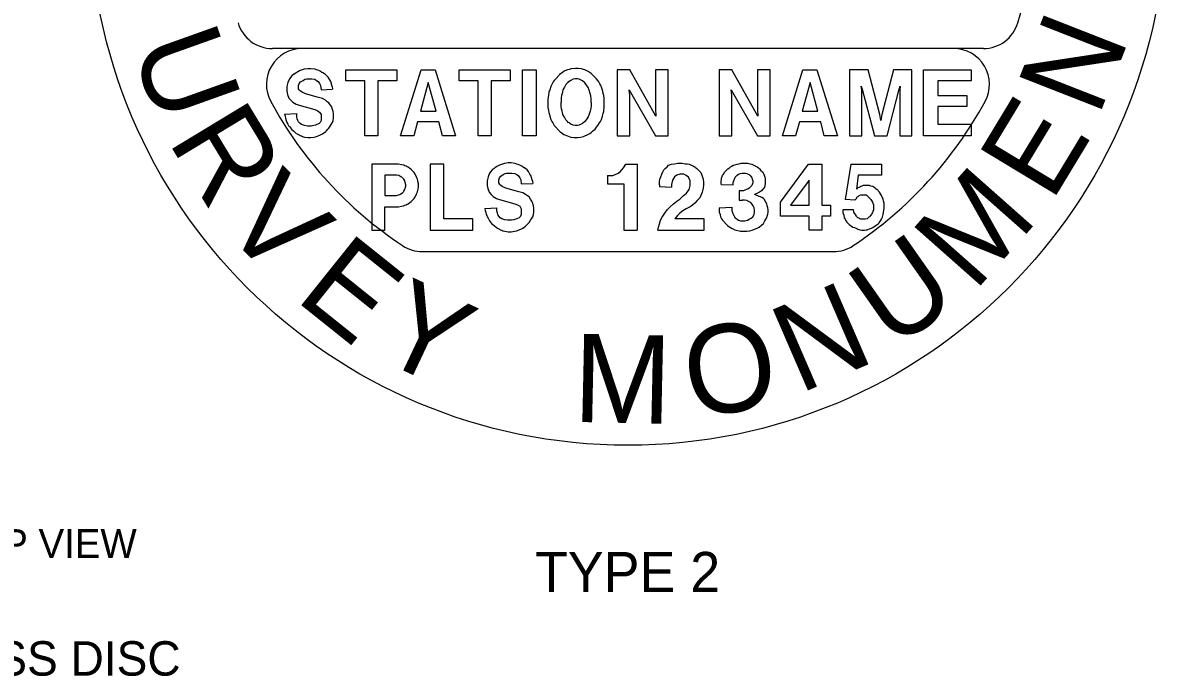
# Model space of a CAD drawing. Extents: x 99862 to 103151, y 100000 to 102076.
# Drawn here: x 100680 to 101477, y 101164 to 101619 of the extents above; entities that cross this region are included whole.
import ezdxf

# ---------------------------------------------------------------- set-up
doc = ezdxf.new("R2010")
doc.units = 0
for name, color, linetype in [('Level 10', 7, 'Continuous'), ('Level 13', 7, 'Continuous'), ('Level 18', 7, 'Continuous'), ('Level 20', 7, 'Continuous'), ('Level 6', 7, 'Continuous')]:
    doc.layers.add(name, color=color, linetype=linetype)

msp = doc.modelspace()

# ---------------------------------------------------------------- linework, layer by layer
at = {"layer": 'Level 13'}
msp.add_line((100958.36, 101459.97), (101244.7, 101459.97), dxfattribs=at)
msp.add_lwpolyline([(101328.45, 101601.53), (100874.62, 101601.53)], dxfattribs=at)
for centre, radius, start, end in [((100874.62, 101576.53), 25, 90, 208.55165), ((101328.45, 101576.53), 25, 331.44835, 90), ((101101.53, 101700), 283.33, 208.55165, 236.34284), ((101101.53, 101700), 283.33, 303.65716, 331.44835), ((100958.36, 101484.97), 25, 236.34284, 270), ((101244.7, 101484.97), 25, 270.00017, 303.65716)]:
    msp.add_arc(centre, radius, start, end, dxfattribs=at)
at = {"layer": 'Level 18'}
msp.add_lwpolyline([(101349.19, 101601.53), (101101.53, 101601.53), (100853.87, 101601.53)], dxfattribs=at)
for centre, radius, start, end in [((101101.53, 101700), 283.33, 343.47705, 20.06426), ((100853.87, 101626.53), 25, 196.52295, 270), ((101349.19, 101626.53), 25, 270, 343.47705)]:
    msp.add_arc(centre, radius, start, end, dxfattribs=at)
at = {"layer": 'Level 20'}
for points in [[(100868.75, 101583.69), (100867.39, 101582.61), (100865.7, 101580.43), (100864.68, 101577.9), (100864.01, 101575), (100864.01, 101571.74), (100864.35, 101569.57), (100865.36, 101567.03), (100866.72, 101565.58), (100868.07, 101564.14), (100870.44, 101562.69), (100872.47, 101561.96), (100883.31, 101559.06), (100885, 101558.33), (100886.69, 101557.25)], [(100868.75, 101583.69), (100869.76, 101584.42), (100870.78, 101585.14), (100871.46, 101585.51), (100872.81, 101586.23), (100874.84, 101586.96), (100876.19, 101587.31), (100878.57, 101587.67), (100879.24, 101587.67), (100880.6, 101587.67), (100883.31, 101587.31), (100884.32, 101586.96), (100885.34, 101586.59), (100887.03, 101585.87), (100888.39, 101585.14), (100889.06, 101584.78), (100890.08, 101584.06)], [(100895.5, 101575), (100894.48, 101578.62), (100893.8, 101579.71), (100892.79, 101581.52), (100891.77, 101582.61), (100890.08, 101584.06)], [(100905.07, 101586.59), (100940.62, 101586.59), (100940.62, 101578.98), (100927.41, 101578.98), (100927.41, 101540.59), (100918.27, 101540.59), (100918.27, 101578.98), (100905.07, 101578.98), (100905.07, 101586.59)], [(100943.17, 101540.59), (100957.39, 101586.59), (100967.21, 101586.59), (100981.43, 101540.59), (100972.29, 101540.59), (100969.91, 101550.37), (100955.02, 101550.37), (100952.31, 101540.59), (100943.17, 101540.59)], [(100983.99, 101586.59), (101019.54, 101586.59), (101019.54, 101578.98), (101006.34, 101578.98), (101006.34, 101540.59), (100997.2, 101540.59), (100997.2, 101578.98), (100983.99, 101578.98), (100983.99, 101586.59)], [(101028.1, 101540.59), (101028.1, 101586.59), (101037.58, 101586.59), (101037.58, 101540.59), (101028.1, 101540.59)], [(101065.44, 101587.67), (101062.06, 101587.31), (101060.7, 101586.96), (101059.34, 101586.59), (101057.65, 101585.87), (101056.97, 101585.51), (101055.96, 101584.78), (101054.95, 101584.06), (101053.93, 101583.33), (101053.59, 101582.97), (101051.22, 101580.43), (101050.21, 101579.35), (101049.52, 101578.26), (101048.85, 101576.81), (101047.83, 101575), (101047.16, 101572.83), (101046.48, 101571.01), (101046.14, 101568.85), (101045.8, 101566.31), (101045.8, 101564.49), (101045.8, 101563.41)], [(101085.08, 101563.41), (101085.08, 101565.58), (101085.08, 101566.67), (101084.74, 101568.85), (101084.4, 101570.29), (101084.06, 101571.74), (101083.39, 101573.91), (101082.71, 101575.73), (101082.03, 101576.81), (101081.35, 101578.26), (101080.68, 101579.35), (101079.66, 101580.43), (101077.63, 101582.61), (101075.94, 101584.06), (101073.9, 101585.51), (101071.53, 101586.59), (101070.52, 101586.96), (101069.17, 101587.31), (101066.79, 101587.67), (101065.1, 101587.67)], [(101093.98, 101586.59), (101093.98, 101540.59), (101102.78, 101540.59), (101102.78, 101569.2), (101102.44, 101572.83), (101120.72, 101540.59), (101129.53, 101540.59), (101129.53, 101586.59), (101120.72, 101586.59), (101120.72, 101559.42), (101121.06, 101554.35), (101102.78, 101586.59), (101093.98, 101586.59)], [(101165.08, 101586.59), (101165.08, 101540.59), (101173.88, 101540.59), (101173.88, 101569.2), (101173.55, 101572.83), (101191.82, 101540.59), (101200.63, 101540.59), (101200.63, 101586.59), (101191.82, 101586.59), (101191.82, 101559.42), (101192.16, 101554.35), (101173.88, 101586.59), (101165.08, 101586.59)], [(101209.19, 101540.59), (101223.41, 101586.59), (101233.23, 101586.59), (101247.45, 101540.59), (101238.31, 101540.59), (101235.93, 101550.37), (101221.04, 101550.37), (101218.33, 101540.59), (101209.19, 101540.59)], [(101256.01, 101586.59), (101256.01, 101540.59), (101264.47, 101540.59), (101264.47, 101572.46), (101264.13, 101575.36), (101264.81, 101573.19), (101273.28, 101540.59), (101282.08, 101540.59), (101290.54, 101573.19), (101291.22, 101575.36), (101290.88, 101572.46), (101290.88, 101540.59), (101299.35, 101540.59), (101299.35, 101586.59), (101286.48, 101586.59), (101278.35, 101555.44), (101277.68, 101551.46), (101277, 101555.44), (101268.87, 101586.59), (101256.01, 101586.59)], [(101307.57, 101540.59), (101307.57, 101586.59), (101340.75, 101586.59), (101340.75, 101578.98), (101317.38, 101578.98), (101317.38, 101568.85), (101337.7, 101568.85), (101337.7, 101561.24), (101317.38, 101561.24), (101317.38, 101548.92), (101340.75, 101548.92), (101340.75, 101540.59), (101307.57, 101540.59)], [(100872.13, 101573.55), (100872.13, 101575.73), (100872.47, 101577.17), (100873.48, 101578.26), (100875.18, 101579.35), (100876.53, 101580.07), (100877.55, 101580.43), (100879.24, 101580.43), (100881.27, 101580.43), (100883.31, 101580.07), (100884.66, 101579.35), (100885.68, 101578.62), (100886.69, 101577.17), (100887.37, 101575.73), (100887.71, 101572.83)], [(100962.47, 101577.9), (100957.05, 101557.98), (100967.89, 101557.98), (100962.47, 101577.9)], [(101075.94, 101564.14), (101075.94, 101564.86), (101075.94, 101566.67), (101075.6, 101568.48), (101075.26, 101570.29), (101074.58, 101572.46), (101073.9, 101574.28), (101072.55, 101576.45), (101071.53, 101577.53), (101069.84, 101578.98), (101068.49, 101579.71), (101067.47, 101580.07), (101066.46, 101580.43), (101065.78, 101580.43), (101064.76, 101580.43), (101063.41, 101580.07), (101061.72, 101579.35), (101060.7, 101578.62), (101060.02, 101578.26), (101059.34, 101577.53), (101058.67, 101576.81), (101058.33, 101576.45), (101057.31, 101574.64), (101056.3, 101572.83), (101055.96, 101571.38), (101055.62, 101570.29), (101055.28, 101568.85), (101054.95, 101567.39), (101054.95, 101566.31), (101054.95, 101564.86), (101054.95, 101564.14)], [(101228.49, 101577.9), (101223.06, 101557.98), (101233.9, 101557.98), (101228.49, 101577.9)], [(100895.5, 101549.65), (100895.83, 101550.01), (100896.17, 101551.46), (100896.51, 101553.27), (100896.51, 101555.08), (100896.51, 101556.17), (100896.17, 101557.62), (100895.5, 101559.79), (100895.16, 101560.87), (100894.14, 101562.32), (100893.13, 101563.77), (100892.11, 101564.49), (100890.75, 101565.58), (100888.73, 101566.67), (100886.01, 101567.39), (100884.32, 101567.76), (100876.88, 101569.93), (100874.5, 101571.01), (100873.48, 101571.74), (100872.81, 101572.46), (100872.13, 101573.55)], [(100887.71, 101572.83), (100895.83, 101573.19)], [(100895.5, 101575), (100895.83, 101573.19)], [(101045.8, 101563.41), (101045.8, 101562.32), (101045.8, 101560.51), (101046.14, 101558.33), (101046.48, 101556.89), (101046.82, 101555.44), (101047.16, 101554.35), (101047.83, 101552.18), (101048.51, 101550.73), (101049.19, 101549.65), (101050.21, 101547.83), (101050.88, 101547.11), (101053.59, 101544.21), (101054.27, 101543.49), (101055.96, 101542.4), (101056.97, 101541.67), (101057.65, 101541.31), (101058.67, 101540.96), (101059.34, 101540.59), (101060.7, 101540.23), (101061.72, 101539.87), (101064.08, 101539.51), (101065.78, 101539.51), (101066.46, 101539.51), (101068.49, 101539.87), (101070.52, 101540.23), (101071.53, 101540.59), (101073.23, 101541.31), (101074.92, 101542.4), (101075.94, 101543.12), (101076.95, 101543.85), (101078.65, 101545.3), (101079.66, 101546.75), (101080.68, 101547.83), (101081.69, 101549.65), (101082.37, 101550.73), (101083.04, 101552.18), (101083.73, 101554.35), (101084.4, 101556.17), (101084.74, 101557.62), (101085.08, 101560.87), (101085.08, 101563.41)], [(101065.78, 101547.83), (101064.76, 101547.83), (101063.41, 101548.2), (101061.72, 101548.92), (101060.7, 101549.65), (101060.02, 101550.01), (101059.34, 101550.73), (101058.67, 101551.46), (101058.33, 101551.82), (101057.31, 101553.63), (101056.3, 101555.44), (101055.96, 101556.89), (101055.62, 101557.98), (101055.28, 101559.42), (101054.95, 101560.87), (101054.95, 101561.96), (101054.95, 101563.41), (101054.95, 101564.14)], [(101075.94, 101564.14), (101075.94, 101563.41), (101075.94, 101561.6), (101075.6, 101559.79), (101075.26, 101557.98), (101074.58, 101555.8), (101073.9, 101553.99), (101072.55, 101551.82), (101071.53, 101550.73), (101069.84, 101549.28), (101068.49, 101548.56), (101067.47, 101548.2), (101066.46, 101547.83), (101065.78, 101547.83)], [(100862.31, 101555.8), (100870.78, 101556.17)], [(100862.31, 101555.8), (100862.66, 101554.35), (100862.99, 101552.9), (100863.33, 101551.46), (100863.67, 101550.73), (100864.01, 101550.01), (100864.68, 101548.92), (100865.36, 101547.47), (100865.7, 101547.11), (100867.05, 101545.3), (100868.75, 101543.85), (100870.44, 101542.4), (100871.12, 101542.04), (100872.47, 101541.31), (100873.15, 101540.96), (100874.17, 101540.59), (100874.84, 101540.23), (100876.19, 101539.87), (100878.57, 101539.51), (100879.58, 101539.51), (100880.6, 101539.51), (100882.97, 101539.87), (100884.66, 101540.23), (100885.68, 101540.59), (100887.37, 101541.31), (100888.73, 101542.04), (100889.74, 101542.76), (100890.75, 101543.49), (100891.44, 101544.21), (100892.45, 101545.3), (100893.13, 101546.02), (100894.14, 101547.47), (100894.82, 101548.56), (100895.5, 101549.65)], [(100883.98, 101548.2), (100882.63, 101547.83), (100880.94, 101547.47), (100879.24, 101547.47), (100878.23, 101547.47), (100876.19, 101547.83), (100874.17, 101548.56), (100873.15, 101549.28), (100872.13, 101550.37), (100871.46, 101551.46), (100871.12, 101552.54), (100870.78, 101553.99), (100870.78, 101556.17)], [(100886.69, 101557.25), (100887.71, 101555.44), (100887.71, 101551.46), (100887.03, 101550.01), (100886.36, 101549.28), (100883.98, 101548.2)], [(100941.7, 101520.92), (100923.08, 101520.92), (100923.08, 101474.92), (100932.22, 101474.92), (100932.22, 101491.21), (100941.7, 101491.21)], [(100941.7, 101491.21), (100943.73, 101491.58), (100945.09, 101491.94), (100946.1, 101492.31), (100947.12, 101492.66), (100947.8, 101493.03), (100948.47, 101493.39), (100949.49, 101494.11), (100950.5, 101494.84), (100951.18, 101495.56), (100951.86, 101496.29), (100952.54, 101497.01), (100953.21, 101498.1), (100953.89, 101499.18), (100954.23, 101499.91), (100954.57, 101500.63), (100954.91, 101501.72), (100955.24, 101502.81), (100955.58, 101504.62), (100955.58, 101505.7), (100955.58, 101507.15), (100955.24, 101508.97), (100955.24, 101509.33), (100954.91, 101510.42), (100954.57, 101511.5), (100953.89, 101512.95), (100953.21, 101514.03), (100952.54, 101515.12), (100951.86, 101515.85), (100951.18, 101516.57), (100950.5, 101517.29), (100949.49, 101518.02), (100948.47, 101518.74), (100947.8, 101519.1), (100947.12, 101519.47), (100946.1, 101519.83), (100945.42, 101520.19), (100943.73, 101520.55), (100941.7, 101520.92)], [(100963.81, 101520.92), (100963.81, 101474.92), (100993.6, 101474.92), (100993.6, 101482.88), (100973.29, 101482.88), (100973.29, 101520.92), (100963.81, 101520.92)], [(101008.25, 101518.02), (101009.27, 101518.74), (101010.29, 101519.47), (101010.96, 101519.83), (101012.32, 101520.55), (101014.34, 101521.28), (101015.7, 101521.64), (101018.07, 101522), (101018.75, 101522), (101020.1, 101522), (101022.81, 101521.64), (101023.83, 101521.28), (101024.84, 101520.92), (101026.54, 101520.19), (101027.89, 101519.47), (101028.56, 101519.1), (101029.59, 101518.38)], [(101087.24, 101512.95), (101088.93, 101512.95), (101090.96, 101512.95), (101092.65, 101513.67), (101094.35, 101514.4), (101096.04, 101515.49), (101097.39, 101516.93), (101098.41, 101518.38), (101100.1, 101520.92)], [(101100.1, 101520.92), (101108.23, 101520.92)], [(101108.23, 101474.92), (101108.23, 101520.92)], [(101123.46, 101506.43), (101123.46, 101508.6), (101123.81, 101510.42), (101124.48, 101512.22), (101125.16, 101514.03), (101125.84, 101515.49), (101126.51, 101516.93), (101127.53, 101518.02), (101128.89, 101519.1), (101129.9, 101520.19), (101131.93, 101520.92), (101133.96, 101521.28), (101135.99, 101521.64), (101137.68, 101521.64), (101139.38, 101521.64), (101141.41, 101521.28), (101142.76, 101521.28), (101144.12, 101520.92), (101145.14, 101520.55), (101145.81, 101520.19), (101147.17, 101519.47), (101147.85, 101519.1), (101148.52, 101518.74), (101148.86, 101518.38), (101149.54, 101518.02), (101149.88, 101517.65), (101150.22, 101517.29), (101150.55, 101516.93), (101150.89, 101516.57), (101151.23, 101516.21), (101151.57, 101515.85), (101152.24, 101515.12), (101152.59, 101514.4), (101152.93, 101513.31), (101153.26, 101512.58), (101153.6, 101511.86), (101153.94, 101510.42), (101154.28, 101508.24), (101154.28, 101506.43), (101153.94, 101504.26)], [(101166.47, 101506.79), (101166.47, 101507.88), (101166.47, 101508.97), (101166.81, 101510.42), (101166.81, 101511.13), (101167.48, 101512.95), (101168.16, 101514.03), (101169.18, 101515.49), (101169.86, 101516.21), (101170.53, 101516.93), (101171.21, 101517.65), (101172.23, 101518.38), (101172.9, 101519.1), (101173.92, 101519.47), (101174.93, 101520.19), (101175.95, 101520.55), (101177.64, 101520.92), (101178.99, 101521.28), (101180.35, 101521.64), (101181.7, 101521.64), (101183.4, 101521.64), (101184.75, 101521.64), (101186.45, 101521.28), (101187.8, 101520.92), (101190.17, 101519.83), (101190.51, 101519.47), (101191.53, 101519.1), (101192.54, 101518.38), (101193.21, 101517.65), (101194.24, 101516.57), (101195.25, 101515.49), (101196.26, 101514.03), (101196.95, 101511.86), (101197.28, 101510.78), (101197.28, 101509.33), (101197.28, 101507.15), (101196.95, 101506.07), (101196.6, 101504.97), (101195.93, 101503.89), (101195.59, 101503.53), (101194.57, 101502.44), (101193.21, 101501.36), (101191.86, 101500.63), (101189.83, 101499.91)], [(101207.78, 101484.7), (101207.78, 101494.47), (101227.42, 101520.92), (101236.56, 101520.92), (101236.56, 101492.31), (101242.65, 101492.31), (101242.65, 101484.7), (101236.56, 101484.7), (101236.56, 101474.92), (101227.76, 101474.92), (101227.76, 101484.7), (101207.78, 101484.7)], [(101256.97, 101520.92), (101252.9, 101496.29)], [(101256.97, 101520.92), (101278.29, 101520.92), (101278.29, 101513.31), (101262.04, 101513.31)], [(100939.67, 101513.31), (100932.22, 101513.31), (100932.22, 101499.18), (100939.67, 101499.18)], [(100939.67, 101499.18), (100940.35, 101499.18), (100941.7, 101499.54), (100942.72, 101499.91), (100943.39, 101500.27), (100944.41, 101500.99), (100945.09, 101501.72), (100945.42, 101502.08), (100946.1, 101503.17), (100946.44, 101504.26), (100946.78, 101505.7), (100946.78, 101506.43), (100946.44, 101508.24), (100946.1, 101509.33), (100945.42, 101510.42), (100944.75, 101511.13), (100944.07, 101511.86), (100943.39, 101512.22), (100942.72, 101512.58), (100942.04, 101512.95), (100940.35, 101513.31), (100940.01, 101513.31), (100939.67, 101513.31)], [(101008.25, 101518.02), (101006.89, 101516.93), (101005.2, 101514.76), (101004.19, 101512.22), (101003.51, 101509.33), (101003.51, 101506.07), (101003.85, 101503.89), (101004.87, 101501.36), (101006.22, 101499.91), (101007.58, 101498.46), (101009.94, 101497.01), (101011.98, 101496.29), (101022.81, 101493.39), (101024.5, 101492.66), (101026.19, 101491.58)], [(101011.63, 101507.88), (101011.63, 101510.05), (101011.98, 101511.5), (101012.99, 101512.58), (101014.68, 101513.67), (101016.04, 101514.4), (101017.05, 101514.76), (101018.75, 101514.76), (101020.78, 101514.76), (101022.81, 101514.4), (101024.16, 101513.67), (101025.18, 101512.95), (101026.19, 101511.5), (101026.87, 101510.05), (101027.21, 101507.15)], [(101035, 101509.33), (101033.98, 101512.95), (101033.31, 101514.03), (101032.29, 101515.85), (101031.28, 101516.93), (101029.59, 101518.38)], [(101087.24, 101512.95), (101087.24, 101507.15), (101098.75, 101507.15), (101098.75, 101474.92), (101107.89, 101474.92)], [(101122.45, 101474.92), (101122.79, 101477.09), (101123.46, 101479.26), (101124.15, 101481.8), (101125.5, 101483.97), (101127.19, 101486.87), (101128.89, 101489.04), (101130.92, 101491.21), (101133.29, 101493.39), (101135.66, 101495.2), (101137.68, 101496.65), (101140.06, 101498.82), (101142.43, 101500.63), (101144.12, 101503.17), (101144.8, 101506.07), (101144.8, 101509.33), (101143.78, 101511.86), (101142.09, 101512.95), (101140.4, 101514.03), (101138.02, 101514.03), (101135.66, 101513.31), (101133.96, 101512.22), (101132.61, 101509.69), (101131.93, 101506.79), (101131.93, 101504.97)], [(101174.93, 101506.43), (101174.93, 101508.24), (101175.27, 101509.33), (101175.61, 101510.05), (101175.95, 101511.13), (101176.29, 101511.86), (101176.97, 101512.58), (101177.64, 101513.31), (101178.66, 101514.03), (101180.02, 101514.4), (101181.03, 101514.76), (101182.38, 101514.76), (101183.4, 101514.76), (101184.42, 101514.4), (101185.43, 101514.03), (101186.11, 101513.67), (101186.78, 101512.95), (101187.46, 101512.22), (101187.8, 101511.5), (101188.14, 101510.42), (101188.48, 101509.33), (101188.48, 101507.88), (101188.14, 101506.79), (101187.8, 101506.07), (101187.12, 101505.34), (101186.11, 101504.26), (101185.09, 101503.53), (101184.07, 101503.17), (101183.06, 101502.81), (101182.04, 101502.44), (101181.37, 101502.44)], [(101262.04, 101513.31), (101260.69, 101503.53)], [(101035, 101483.97), (101035.34, 101484.33), (101035.67, 101485.78), (101036.02, 101487.6), (101036.02, 101489.4), (101036.02, 101490.49), (101035.67, 101491.94), (101035, 101494.11), (101034.66, 101495.2), (101033.65, 101496.65), (101032.63, 101498.1), (101031.61, 101498.82), (101030.26, 101499.91), (101028.23, 101500.99), (101025.52, 101501.72), (101023.83, 101502.08), (101016.38, 101504.26), (101014.01, 101505.34), (101012.99, 101506.07), (101012.32, 101506.79), (101011.63, 101507.88)], [(101027.21, 101507.15), (101035.34, 101507.52)], [(101035, 101509.33), (101035.34, 101507.52)], [(101123.46, 101506.43), (101123.46, 101505.34)], [(101123.46, 101505.34), (101131.93, 101504.97)], [(101153.94, 101504.26), (101153.26, 101501.36), (101152.24, 101499.18), (101151.57, 101497.37), (101149.88, 101495.56), (101148.18, 101493.75), (101146.49, 101492.31), (101144.8, 101491.21), (101142.09, 101489.76), (101139.72, 101488.31), (101137.68, 101486.87), (101135.99, 101485.06), (101134.3, 101482.88)], [(101166.47, 101506.79), (101174.93, 101506.43)], [(101227.76, 101509.69), (101214.89, 101492.31), (101227.76, 101492.31), (101227.76, 101509.69)], [(101251.21, 101489.04), (101251.21, 101487.96), (101251.21, 101487.23), (101251.55, 101486.51), (101251.89, 101485.42), (101252.22, 101483.61), (101252.9, 101482.53), (101253.24, 101481.8), (101253.92, 101481.08), (101253.92, 101480.71), (101254.59, 101479.99), (101255.27, 101479.26), (101255.61, 101478.9), (101256.29, 101478.54), (101257.3, 101477.81), (101258.32, 101477.09), (101259.33, 101476.73), (101261.02, 101476), (101261.71, 101475.64), (101263.06, 101475.28), (101264.42, 101474.92), (101265.43, 101474.92), (101266.44, 101474.92), (101267.47, 101475.28), (101268.14, 101475.28), (101269.16, 101475.64), (101270.51, 101476), (101271.19, 101476.37), (101272.2, 101476.73), (101273.22, 101477.45), (101274.23, 101478.18), (101275.93, 101479.26), (101276.6, 101479.99), (101277.62, 101481.43), (101278.29, 101482.53), (101278.98, 101483.97), (101279.31, 101485.78), (101279.65, 101487.6), (101279.99, 101490.13), (101279.99, 101493.03), (101279.99, 101493.75), (101279.65, 101495.2), (101279.31, 101496.65), (101278.64, 101498.1), (101278.29, 101499.18), (101277.62, 101500.27), (101276.94, 101501.36), (101275.93, 101502.44), (101275.59, 101502.81), (101274.57, 101503.53), (101273.9, 101504.26), (101272.88, 101504.97), (101272.2, 101505.34), (101270.85, 101505.7), (101269.83, 101506.07), (101268.48, 101506.07), (101267.12, 101506.07), (101266.11, 101506.07), (101265.43, 101506.07), (101264.42, 101505.7), (101263.73, 101505.34), (101263.06, 101504.97), (101262.38, 101504.62), (101261.37, 101504.26), (101260.69, 101503.53)], [(101165.12, 101490.49), (101165.12, 101487.6), (101165.79, 101485.78), (101166.13, 101484.33), (101166.81, 101482.88), (101167.48, 101481.8), (101168.5, 101480.71), (101167.82, 101481.43), (101170.19, 101478.9), (101170.87, 101478.18), (101171.89, 101477.45), (101172.9, 101476.73), (101174.26, 101476), (101175.95, 101475.28), (101180.02, 101474.19), (101181.03, 101474.19), (101182.72, 101474.19), (101184.42, 101474.19), (101186.45, 101474.55), (101188.14, 101474.92), (101189.83, 101475.64), (101191.53, 101476.37), (101192.88, 101477.09), (101194.57, 101478.54), (101195.93, 101479.63), (101196.95, 101481.43), (101197.62, 101482.53), (101198.3, 101483.61), (101198.64, 101484.7), (101198.97, 101486.15), (101199.31, 101487.6), (101199.31, 101489.04), (101198.97, 101490.49), (101198.64, 101491.94), (101198.3, 101493.03), (101197.96, 101494.11), (101197.28, 101495.2), (101196.6, 101496.29), (101195.93, 101497.01), (101194.91, 101497.74), (101193.9, 101498.1), (101192.88, 101498.46), (101191.53, 101499.18), (101189.83, 101499.91)], [(101173.92, 101490.86), (101173.92, 101488.68), (101174.59, 101486.51), (101175.27, 101485.06), (101176.29, 101483.61), (101177.64, 101482.53), (101178.66, 101481.8), (101180.02, 101481.43), (101181.7, 101481.43), (101183.06, 101481.43), (101184.75, 101481.8), (101186.11, 101482.53), (101187.46, 101483.25), (101188.48, 101484.33), (101189.49, 101485.78), (101189.83, 101487.23), (101189.83, 101488.68), (101189.49, 101490.49), (101188.81, 101491.94), (101187.8, 101493.39), (101187.12, 101494.11), (101186.45, 101494.47), (101184.42, 101495.56), (101182.72, 101495.92), (101181.37, 101495.92)], [(101181.37, 101502.44), (101178.99, 101502.44), (101178.99, 101495.92), (101181.37, 101495.92)], [(101259.68, 101495.92), (101252.9, 101496.29)], [(101259.68, 101495.92), (101260.69, 101497.01), (101261.02, 101497.74), (101261.37, 101498.1), (101262.04, 101498.46), (101262.72, 101499.18), (101263.73, 101499.54), (101264.07, 101499.54), (101264.42, 101499.54), (101265.43, 101499.54), (101265.77, 101499.54), (101266.44, 101499.54), (101267.47, 101499.54), (101268.14, 101499.18), (101268.48, 101498.82), (101268.81, 101498.46), (101269.49, 101497.74), (101269.83, 101497.37), (101270.17, 101497.01), (101270.85, 101496.29), (101271.19, 101495.56), (101271.86, 101494.47), (101272.2, 101493.75), (101272.54, 101492.66), (101272.54, 101491.58), (101272.54, 101490.86), (101272.54, 101490.13), (101272.54, 101489.04), (101272.2, 101487.96), (101271.86, 101487.23), (101271.52, 101486.51), (101271.19, 101486.15), (101270.85, 101485.42), (101270.51, 101485.06), (101269.83, 101484.33), (101269.49, 101483.97), (101268.81, 101483.25), (101268.14, 101482.88), (101266.78, 101482.53), (101265.77, 101482.53), (101265.09, 101482.53), (101264.07, 101482.53), (101263.73, 101482.53), (101263.06, 101482.88), (101262.38, 101483.25), (101261.71, 101483.61), (101261.02, 101484.33), (101260.69, 101484.7), (101260.01, 101485.78), (101259.33, 101486.87), (101259, 101487.6), (101259, 101487.96), (101258.66, 101489.04)], [(101001.82, 101490.13), (101010.29, 101490.49)], [(101001.82, 101490.13), (101002.16, 101488.68), (101002.5, 101487.23), (101002.83, 101485.78), (101003.17, 101485.06), (101003.51, 101484.33), (101004.19, 101483.25), (101004.87, 101481.8), (101005.2, 101481.43), (101006.56, 101479.63), (101008.25, 101478.18), (101009.94, 101476.73), (101010.62, 101476.37), (101011.98, 101475.64), (101012.65, 101475.28), (101013.67, 101474.92), (101014.34, 101474.55), (101015.7, 101474.19), (101018.07, 101473.83), (101019.09, 101473.83), (101020.1, 101473.83), (101022.47, 101474.19), (101024.16, 101474.55), (101025.18, 101474.92), (101026.87, 101475.64), (101028.23, 101476.37), (101029.24, 101477.09), (101030.26, 101477.81), (101030.94, 101478.54), (101031.95, 101479.63), (101032.63, 101480.35), (101033.65, 101481.8), (101034.32, 101482.88), (101035, 101483.97)], [(101023.49, 101482.53), (101022.13, 101482.16), (101020.44, 101481.8), (101018.75, 101481.8), (101017.73, 101481.8), (101015.7, 101482.16), (101013.67, 101482.88), (101012.65, 101483.61), (101011.63, 101484.7), (101010.96, 101485.78), (101010.62, 101486.87), (101010.29, 101488.31), (101010.29, 101490.49)], [(101026.19, 101491.58), (101027.21, 101489.76), (101027.21, 101485.78), (101026.54, 101484.33), (101025.86, 101483.61), (101023.49, 101482.53)], [(101165.12, 101490.49), (101173.92, 101490.86)], [(101258.66, 101489.04), (101251.21, 101489.04)], [(101122.45, 101474.92), (101154.62, 101474.92), (101154.62, 101482.88), (101134.3, 101482.88)]]:
    msp.add_lwpolyline(points, dxfattribs=at)
at = {"layer": 'Level 6'}
msp.add_circle((101101.53, 101700), 375, dxfattribs=at)

# ---------------------------------------------------------------- texts
at = {"layer": 'Level 10'}
for s, rotation, p in [('N', 68.59815, (101429.27, 101553.05)), ('U', 289.66641, (100755.21, 101602.45)), ('E', 58.82128, (101396.63, 101493.7)), ('R', 301.20479, (100780.53, 101537.48)), ('V', 314.61462, (100816.91, 101477.67)), ('M', 48.48341, (101342.83, 101431.32)), ('U', 35.07358, (101285.67, 101390.93)), ('E', 321.31953, (100868.7, 101426.84)), ('Y', 334.72936, (100923.69, 101387.23)), ('N', 23.40658, (101220.79, 101360.51)), ('O', 8.25393, (101145.19, 101343.82)), ('M', 358.80062, (101063.03, 101341.35))]:
    msp.add_text(s, height=61.5, rotation=rotation, dxfattribs=at).set_placement(p)
at = {"layer": 'Level 20'}
for s, height, p in [('TOP VIEW', 20, (100628.52, 101246.57)), ('TYPE 2', 28, (101036.81, 101222.69)), ('BRASS DISC', 24, (100595.5, 101164.46))]:
    msp.add_text(s, height=height, dxfattribs=at).set_placement(p)

doc.saveas('drawing.dxf')
